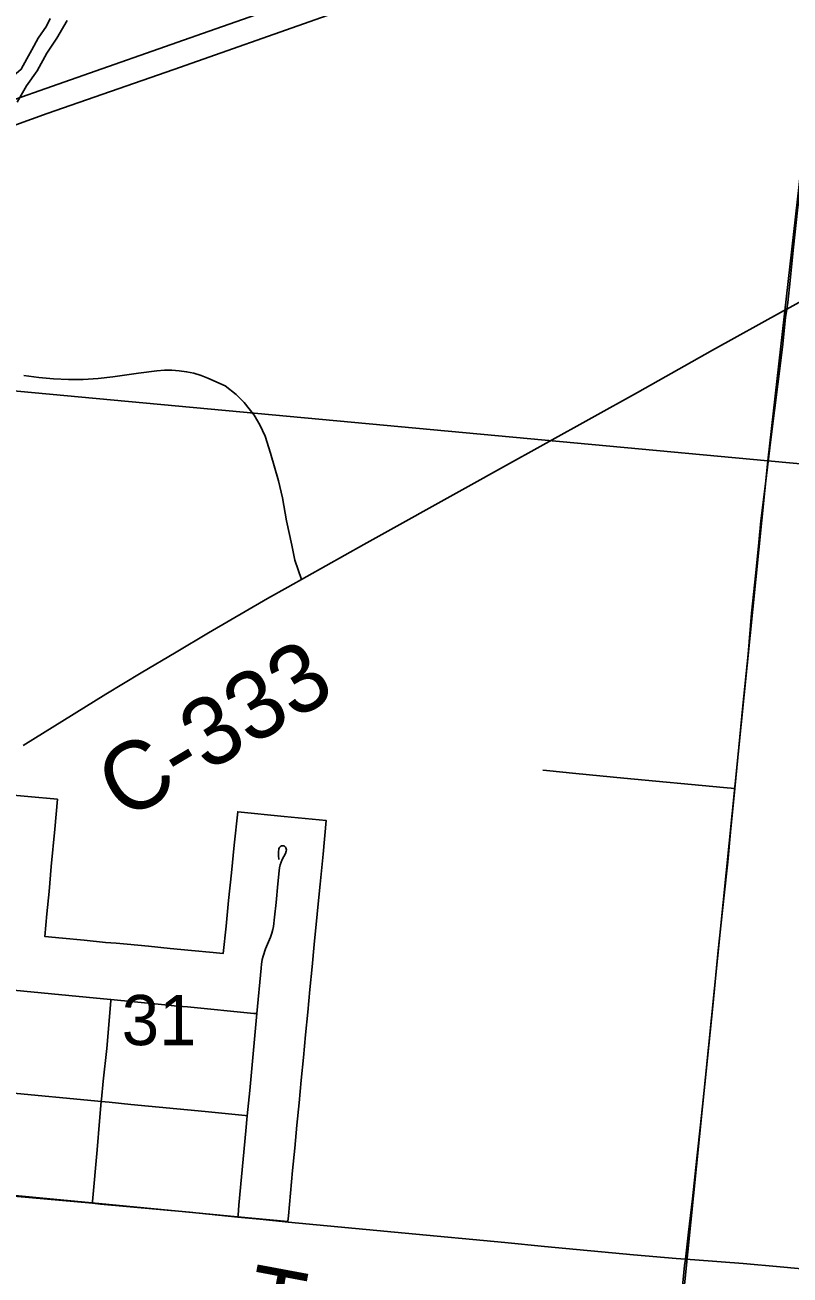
# Model space of a CAD drawing. Extents: x 0 to 34, y 0 to 22.
# Drawn here: x 3.271 to 3.909, y 14.717 to 15.759 of the extents above; entities that cross this region are included whole.
import ezdxf

# ---------------------------------------------------------------- set-up
doc = ezdxf.new("R2010")
doc.units = 0
for name, color, linetype in [('GM_X_City_Street', 7, 'Continuous'), ('GM_X_County_Road', 7, 'Continuous'), ('GM_X_County_Road_Text', 7, 'Continuous'), ('GM_X_Interstate_Route', 7, 'Continuous'), ('GM_X_Minor_Lake', 7, 'Continuous'), ('GM_X_Minor_River', 7, 'Continuous'), ('GM_X_Section', 7, 'Continuous'), ('GM_X_Section_Text', 7, 'Continuous'), ('GM_X_Township_Road', 7, 'Continuous'), ('GM_X_Township_Road_Text', 7, 'Continuous'), ('SC_Shading1', 7, 'Continuous')]:
    doc.layers.add(name, color=color, linetype=linetype)

msp = doc.modelspace()

# ---------------------------------------------------------------- linework, layer by layer
at = {"layer": 'GM_X_City_Street'}
for points in [[(3.4482, 14.7653), (3.4484, 14.767), (3.4491, 14.7753), (3.4548, 14.8372), (3.4561, 14.8498), (3.4582, 14.8707), (3.4611, 14.9014), (3.4639, 14.9349), (3.4676, 14.9729), (3.4679, 14.9761), (3.4685, 14.9799), (3.4693, 14.9829), (3.4713, 14.9888), (3.4754, 14.9987), (3.4766, 15.002), (3.4775, 15.005), (3.4778, 15.0075), (3.4787, 15.0152), (3.4801, 15.0275), (3.4816, 15.043), (3.4827, 15.054), (3.483, 15.0564), (3.4835, 15.059), (3.4852, 15.0632), (3.4878, 15.0682), (3.4886, 15.0702), (3.4887, 15.0713), (3.4886, 15.0723), (3.4883, 15.0731), (3.4879, 15.0737), (3.487, 15.0745), (3.4862, 15.0748), (3.4853, 15.0748), (3.4845, 15.0746), (3.4837, 15.0743), (3.4831, 15.0737), (3.4827, 15.0731), (3.4824, 15.0722), (3.482, 15.0695), (3.482, 15.0667), (3.4824, 15.0634)], [(3.118, 14.9664), (3.1233, 14.9669), (3.1276, 14.9667), (3.1309, 14.9666), (3.138, 14.9659), (3.1659, 14.9633), (3.2407, 14.9563), (3.3363, 14.9473), (3.3424, 14.9467), (3.3846, 14.9426), (3.3979, 14.9412), (3.4061, 14.9405), (3.4616, 14.9351), (3.4639, 14.9349)], [(3.327, 14.7768), (3.3271, 14.7782), (3.3309, 14.8213), (3.3329, 14.8452), (3.3343, 14.8617), (3.3345, 14.8635), (3.336, 14.8786), (3.3389, 14.9057), (3.3423, 14.9456), (3.3424, 14.9467)], [(3.2584, 14.8688), (3.3286, 14.8622), (3.3343, 14.8617), (3.3409, 14.8611), (3.359, 14.8592), (3.421, 14.8532), (3.4488, 14.8505), (3.4544, 14.8499), (3.4561, 14.8498)]]:
    msp.add_lwpolyline(points, dxfattribs=at)
at = {"layer": 'GM_X_County_Road'}
for points in [[(3.9058, 15.522), (3.9664, 15.5555), (4.0169, 15.5836), (4.0723, 15.6143), (4.1238, 15.6432), (4.1483, 15.6568), (4.2249, 15.6993)], [(3.2692, 15.1584), (3.3118, 15.1848), (3.3382, 15.2012), (3.3675, 15.2189), (3.3969, 15.2362), (3.4236, 15.2521), (3.473, 15.2809), (3.4899, 15.2904), (3.5531, 15.3259), (3.6428, 15.3755), (3.6672, 15.3891), (3.7813, 15.4526), (3.8438, 15.4877), (3.9032, 15.5206), (3.9058, 15.522)]]:
    msp.add_lwpolyline(points, dxfattribs=at)
at = {"layer": 'GM_X_Interstate_Route'}
for points in [[(2.8746, 15.5607), (2.887, 15.565), (2.8934, 15.5672), (2.9643, 15.5921), (3.0288, 15.6148), (3.1138, 15.6446), (3.2017, 15.6756), (3.2065, 15.6773), (3.2984, 15.7096), (3.4186, 15.7518), (3.5417, 15.7949), (3.6706, 15.8404), (3.7176, 15.8565), (3.7471, 15.8661), (3.7739, 15.8741), (3.8008, 15.8814), (3.8219, 15.8865), (3.8492, 15.8925), (3.8797, 15.8983), (3.9042, 15.9025), (3.9288, 15.906)], [(2.8821, 15.5432), (2.885, 15.5442), (2.9673, 15.5719), (3.0022, 15.5838), (3.0579, 15.6034), (3.1253, 15.6269), (3.1843, 15.6479), (3.2147, 15.6585), (3.2366, 15.6661), (3.2893, 15.685), (3.3949, 15.7218), (3.5179, 15.7651), (3.6586, 15.8144), (3.7084, 15.8318), (3.7468, 15.8445), (3.7705, 15.8519), (3.7945, 15.8586), (3.8246, 15.8662), (3.8519, 15.8724), (3.8763, 15.8773), (3.8977, 15.881), (3.9223, 15.8846)]]:
    msp.add_lwpolyline(points, dxfattribs=at)
at = {"layer": 'GM_X_Minor_Lake'}
msp.add_lwpolyline([(3.1979, 15.7653), (3.197, 15.7535), (3.1962, 15.7455), (3.1957, 15.7364), (3.1944, 15.7277), (3.192, 15.719), (3.1923, 15.7114), (3.2002, 15.7045), (3.2082, 15.7029), (3.2177, 15.7035), (3.2257, 15.7057), (3.2337, 15.7082), (3.2425, 15.7108), (3.2505, 15.7126), (3.2596, 15.7151), (3.2677, 15.7219), (3.2723, 15.7306), (3.2766, 15.7381), (3.2817, 15.7479), (3.2886, 15.7577), (3.2917, 15.7641)], dxfattribs=at)
at = {"layer": 'GM_X_Minor_River'}
msp.add_lwpolyline([(3.2643, 15.6946), (3.2721, 15.7082), (3.281, 15.7206), (3.2891, 15.7353), (3.2972, 15.7477), (3.3058, 15.7624)], dxfattribs=at)
at = {"layer": 'GM_X_Section'}
for points in [[(2.9781, 16.4922), (4.0036, 16.3979), (3.89, 15.3957), (2.8777, 15.4895)], [(4.0036, 16.3979), (4.9634, 16.3122), (4.8743, 15.3051), (3.89, 15.3957)], [(2.8777, 15.4895), (3.89, 15.3957), (3.7885, 14.3929), (2.8001, 14.4908), (2.7782, 14.493)], [(3.89, 15.3957), (4.8743, 15.3051), (4.7835, 14.3098), (3.8021, 14.3916), (3.7885, 14.3929)]]:
    msp.add_lwpolyline(points, close=True, dxfattribs=at)
at = {"layer": 'GM_X_Township_Road'}
msp.add_line((3.4852, 14.7617), (3.4902, 14.7612), dxfattribs=at)
for points in [[(3.9058, 15.522), (3.9066, 15.5274), (3.9086, 15.5459), (3.9115, 15.5737), (3.9148, 15.6045), (3.9181, 15.6323), (3.9186, 15.6385)], [(3.8624, 15.1225), (3.8692, 15.1913), (3.8736, 15.2345), (3.8765, 15.2685), (3.88, 15.3022), (3.8826, 15.3274), (3.8842, 15.3456), (3.888, 15.3763), (3.8924, 15.4134), (3.8984, 15.4596), (3.9023, 15.4904), (3.9048, 15.5151), (3.9058, 15.522)], [(3.2699, 15.4667), (3.2822, 15.465), (3.2945, 15.4639), (3.3069, 15.4633), (3.3193, 15.4634), (3.3317, 15.4641), (3.344, 15.4655), (3.3655, 15.4687), (3.3808, 15.4707), (3.387, 15.4711), (3.3932, 15.4711), (3.3994, 15.4707), (3.4055, 15.4698), (3.4116, 15.4685), (3.4175, 15.4667), (3.4233, 15.4645), (3.4375, 15.4581), (3.4468, 15.4509), (3.4536, 15.4441), (3.4619, 15.4337), (3.4664, 15.4256), (3.4709, 15.4161), (3.4755, 15.4021), (3.4822, 15.3789), (3.4854, 15.3647), (3.4888, 15.3455), (3.4931, 15.3254), (3.4958, 15.3128), (3.5013, 15.2968)], [(3.7024, 15.1377), (3.7054, 15.1374), (3.73, 15.1351), (3.77, 15.1312), (3.8531, 15.1234), (3.8624, 15.1225)], [(3.8213, 14.7303), (3.824, 14.7527), (3.8271, 14.7805), (3.8308, 14.8145), (3.8338, 14.8422), (3.8374, 14.8762), (3.8441, 14.941), (3.8486, 14.9874), (3.8537, 15.0337), (3.8566, 15.0615), (3.8592, 15.0892), (3.8616, 15.114), (3.8624, 15.1225)], [(3.1723, 14.7912), (3.2008, 14.7886), (3.2255, 14.7862), (3.2645, 14.7825), (3.327, 14.7768)], [(3.327, 14.7768), (3.3337, 14.7761), (3.3801, 14.7719), (3.4079, 14.7693), (3.4482, 14.7653)], [(3.4482, 14.7653), (3.4666, 14.7635), (3.4852, 14.7617)], [(3.4902, 14.7612), (3.5877, 14.7519), (3.6707, 14.7441), (3.7039, 14.7409), (3.7779, 14.7338), (3.8137, 14.7309), (3.8213, 14.7303)], [(3.8164, 14.6817), (3.8206, 14.725), (3.8213, 14.7303)], [(3.8213, 14.7303), (3.8293, 14.7296), (3.8694, 14.7266), (3.9003, 14.7239), (3.9302, 14.7212)]]:
    msp.add_lwpolyline(points, dxfattribs=at)
at = {"layer": 'SC_Shading1'}
msp.add_lwpolyline([(3.172, 14.7918), (3.3265, 14.7771), (3.4478, 14.7656), (3.4899, 14.7616), (3.4903, 14.7664), (3.4939, 14.8041), (3.4957, 14.8229), (3.4975, 14.8418), (3.4993, 14.8606), (3.5011, 14.8795), (3.5029, 14.8983), (3.5047, 14.9172), (3.5065, 14.936), (3.5083, 14.9549), (3.5101, 14.9738), (3.5119, 14.9926), (3.5144, 15.0177), (3.5144, 15.018), (3.5168, 15.0427), (3.5192, 15.0678), (3.5219, 15.0957), (3.4867, 15.0992), (3.4481, 15.1031), (3.4452, 15.0754), (3.4429, 15.0522), (3.4405, 15.0291), (3.4384, 15.0077), (3.4361, 14.9851), (3.4275, 14.9859), (3.4096, 14.9876), (3.3917, 14.9893), (3.3738, 14.991), (3.3559, 14.9927), (3.3467, 14.9935), (3.3379, 14.9943), (3.32, 14.996), (3.3021, 14.9977), (3.2873, 14.9991), (3.289, 15.018), (3.2908, 15.0368), (3.2927, 15.0576), (3.2955, 15.0887), (3.2978, 15.1135), (3.2731, 15.1158), (3.242, 15.1186)], dxfattribs=at)

# ---------------------------------------------------------------- texts
at = {"layer": 'GM_X_County_Road_Text'}
msp.add_text('C-333', height=0.05682, rotation=30.829, dxfattribs=at).set_placement((3.3538, 15.0947))
at = {"layer": 'GM_X_Section_Text'}
msp.add_text('31', height=0.04186, rotation=0, dxfattribs=at).set_placement((3.3514, 14.9086))
at = {"layer": 'GM_X_Township_Road_Text'}
msp.add_text('T', height=0.0568, rotation=349.4293, dxfattribs=at).set_placement((3.4526, 14.6703))

doc.saveas('drawing.dxf')
